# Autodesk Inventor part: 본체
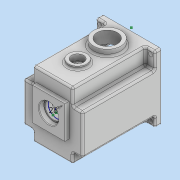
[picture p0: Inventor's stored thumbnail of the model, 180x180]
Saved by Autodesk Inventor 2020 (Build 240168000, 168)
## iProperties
Created: 2022-01
Part Number: 본체
Material: 일반
Document SubType Name: Modeling
Designer: user
Density: 1 g/cm^3
Appearance: 기본값
Author: user
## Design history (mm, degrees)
sketch "스케치1"
  geometry: 1 further point
sketch "스케치2"
  geometry: L1 (-49, 55)-(49, 55); L2 (49, 55)-(49, -55); L3 (49, -55)-(-49, -55); L4 (-49, -55)-(-49, 55); L5 (-49, 55)-(49, -55); L6 (49, 55)-(-49, -55); 1 further point
  constraints: 12 end point, 2 midpoint, 2 parallel, 1 horizontal, 1 perpendicular
  dimensions: "d0" = 98 distance of L2.end L3.end; "d1" = 110 distance of L1.end L2.end
extrude "돌출1" new body sketch "스케치2" distance "d2" = 10; taper "d3" = 0 deg
sketch "스케치3"
  geometry: L1 (49, -55)-(49, 55) reference; L2 (49, 55)-(-49, 55) reference; L3 (-49, 55)-(-49, -55) reference; L4 (-49, -55)-(49, -55) reference; L5 (49, -55)-(49, 55) reference; L6 (49, 55)-(33, 55); L7 (33, 55)-(33, 28); L8 (33, 28)-(49, 28); L9 (49, 28)-(49, 55); L10 (49, -55)-(33, -55); L11 (33, -55)-(33, -38); L12 (33, -38)-(49, -38); L13 (49, -38)-(49, -55); L14 (-49, -55)-(49, -55) reference; L15 (-49, -55)-(-33, -55); L16 (-33, -55)-(-33, -38); L17 (-33, -38)-(-49, -38); L18 (-49, -38)-(-49, -55); L19 (-49, 55)-(-49, -55) reference; L20 (-49, 55)-(-33, 55); L21 (-33, 55)-(-33, 28); L22 (-33, 28)-(-49, 28); L23 (-49, 28)-(-49, 55); 9 further points
  constraints: 32 end point, 8 parallel, 4 horizontal, 4 perpendicular, 1 point on line
  dimensions: "d4" = 27 distance of L6.end L7.end; "d5" = 16 distance of L7.end L8.end; "d6" = 17 distance of L10.end L11.end; "d7" = 16 distance of L11.end L12.end; "d8" = 27 distance of L20.end L21.end; "d9" = 16 distance of L21.end L22.end; "d10" = 16 distance of L16.end L17.end
extrude "돌출2" join sketch "스케치3" distance "d11" = 120; taper "d12" = 0 deg
sketch "스케치4"
  geometry: 1 further point
sketch "스케치5"
  geometry: L1 (49, -55)-(-49, -55) reference; L2 (-26, 48)-(26, 48); L3 (26, 48)-(26, 27.588); L4 (26, 27.588)-(-26, 27.588); L5 (-26, 27.588)-(-26, 48); C1 r 45 at (0, -5); 3 further points
  constraints: 8 end point, 2 parallel, 1 centre point, 1 horizontal, 1 perpendicular, 1 vertical alignment
  dimensions: "d13" = 90 diameter of C1; "d14" = 50 distance from line of L1 C1.centre; "d15" = 53 distance from line of L2 C1.centre; "d16" = 52 distance of L2.start L2.end; "d17" = 26 horizontal distance of C1.centre L2.start
extrude "돌출3" cut sketch "스케치5" distance "d18" = 9; taper "d19" = 0 deg
sketch "스케치6" dims "d27" = 8, "d28" = 8
  geometry: L1 (-26, 31.729)-(-26, 48) reference; L2 (26, 48)-(26, 31.729) reference; L3 (-26, 48)-(26, 48) reference; L4 (-23, 45)-(23, 45); L5 (23, 45)-(23, 21.058); L6 (23, 21.058)-(-23, 21.058); L7 (-23, 21.058)-(-23, 45); L8 (-35.778, -1.006)-(-41.81, -1.006); L9 (-35.778, -8.994)-(-41.81, -8.994); L10 (35.778, -1.006)-(42, -1.006); L11 (35.778, -8.994)-(41.81, -8.994); A1 r 45 centre (0, -5) between (-26, 31.729) and (26, 31.729) reference; A2 r 36 centre (0, -5) between (36, -5) and (-36, -5); A3 r 42 centre (0, -5) between (-41.81, -8.994) and (41.81, -8.994); A4 r 42 centre (0, -5) between (41.81, -1.006) and (-41.81, -1.006); 7 further points
  constraints: 16 end point, 10 point on circle, 4 horizontal, 3 centre point, 2 coincident, 2 horizontal alignment, 2 parallel, 1 perpendicular, 1 point on line, 6 other
  dimensions: "d21" = 46 distance of L4.start L4.end; "d22" = 23 distance from line of A1.centre L7; "d23" = 50 distance from line of A1.centre L4; "d26" = 72 diameter of A2
  node "투영된 루프2"
extrude "돌출4" cut sketch "스케치6" distance "d29" = 112; taper "d30" = 0 deg
fillet "모깎기1" dims "d31" = 3
sketch "스케치8"
  geometry: L1 (98, 0)-(0, 0) reference; C1 r 22.5 at (49, -40); C2 r 15 at (49, -89); 2 further points
  constraints: 2 centre point, 2 vertical alignment, 1 midpoint
  dimensions: "d32" = 45 diameter of C1; "d33" = 30 diameter of C2; "d34" = 40 distance of C1.centre point (49, 0); "d35" = 49 distance of C1.centre C2.centre
extrude "돌출5" join sketch "스케치8" distance "d36" = 10; taper "d37" = 0 deg
sketch "스케치9"
  geometry: C1 r 22.5 at (49, -40) reference; C2 r 15 at (49, -89); 1 further point
  constraints: 1 centre point, 1 vertical alignment
  dimensions: "d38" = 30 diameter of C2; "d39" = 49 distance of C1.centre C2.centre
extrude "돌출6" join sketch "스케치9" distance "d40" = 5; taper "d41" = 0 deg
sketch "스케치10"
  geometry: 1 further point
sketch "스케치11"
  geometry: C1 r 21 at (0, 6); C2 r 15 at (0, -25); C3 r 42 at (0, -5); A1 r 42 centre (0, -5) between (-23, 30.143) and (-41.319, 2.532) reference; 3 further points
  constraints: 3 centre point, 2 vertical alignment, 1 coincident
  dimensions: "d42" = 42 diameter of C1; "d43" = 30 diameter of C2; "d44" = 20 distance of C2.centre C3.centre; "d45" = 11 distance of C1.centre C3.centre
sketch "스케치12"
  geometry: C1 r 22.5 at (0, 0) reference; 2 further points
  constraints: 1 coincident
hole "구멍1" sketch "스케치12" at (0, 0) diameter "d46" = 33.376; stored, may be unused: countersink angle "d50" = 90 deg, drill point angle "d52" = 118 deg; dims "d47" = 70, "d48" = 4, "d49" = 2, "d51" = 77.3
extrude "돌출7" join sketch "스케치11" distance "d53" = 7; taper "d54" = 0 deg
sketch "스케치13"
  geometry: C1 r 11 at (0, -25); A1 r 15 centre (0, -25) between (-8.978, -12.984) and (8.978, -12.984) reference; 1 further point
  constraints: 1 centre point, 1 coincident
  dimensions: "d55" = 22 diameter of C1
extrude "돌출8" cut sketch "스케치13" distance "d56" = 7; taper "d57" = 0 deg
sketch "스케치14"
  geometry: C1 r 17.5 at (0, 6); A1 r 21 centre (0, 6) between (8.978, -12.984) and (-8.978, -12.984) reference; 1 further point
  constraints: 1 centre point, 1 coincident
  dimensions: "d58" = 35 diameter of C1
extrude "돌출9" cut sketch "스케치14" distance "d59" = 10; taper "d60" = 0 deg
sketch "스케치15"
  geometry: C1 r 11 at (0, 0) reference; C2 r 9.5 at (0, 0); 1 further point
  constraints: 1 centre point, 1 coincident
  dimensions: "d61" = 19 diameter of C2
extrude "돌출10" cut sketch "스케치15" distance "d62" = 3; taper "d63" = 0 deg
sketch "스케치16"
  geometry: C1 r 17.5 at (0, 0) reference; C2 r 14 at (0, 0); 1 further point
  constraints: 1 centre point, 1 coincident
  dimensions: "d64" = 28 diameter of C2
sketch "스케치17"
  geometry: 1 further point
sketch "스케치18"
  geometry: 1 further point
sketch "스케치19"
  geometry: L1 (-27, 33)-(27, 33); L2 (27, 33)-(27, -21); L3 (27, -21)-(-27, -21); L4 (-27, -21)-(-27, 33); L5 (-27, 33)-(27, -21); L6 (27, 33)-(-27, -21); 4 further points
  constraints: 12 end point, 3 midpoint, 2 parallel, 1 coincident, 1 horizontal, 1 perpendicular
  dimensions: "d65" = 54 distance of L2.end L3.end; "d66" = 54 distance of L1.end L2.end
extrude "돌출11" join sketch "스케치19" distance "d67" = 7; taper "d68" = 0 deg
sketch "스케치20"
  geometry: C1 r 16 at (0, 6); A1 r 21 centre (0, 6) between (8.978, -12.984) and (-8.978, -12.984) reference; 1 further point
  constraints: 1 centre point, 1 coincident
  dimensions: "d69" = 32 diameter of C1
extrude "돌출12" cut sketch "스케치20" distance "d70" = 8.3; taper "d71" = 0 deg
sketch "스케치21"
  geometry: C1 r 16 at (0, 0) reference; C2 r 14 at (0, 0); 1 further point
  constraints: 1 centre point, 1 coincident
  dimensions: "d72" = 28 diameter of C2
extrude "돌출13" cut sketch "스케치21" distance "d73" = 8.3; taper "d74" = 0 deg
sketch "스케치22"
  geometry: 1 further point
sketch "스케치23"
  geometry: C1 r 15 at (23, 80) reference; C2 r 15 at (23, 80); 1 further point
  constraints: 1 centre point, 1 coincident
  dimensions: "d75" = 30 diameter of C2
extrude "돌출14" cut sketch "스케치23" distance "d76" = 5; taper "d77" = 0 deg
sketch "스케치24"
  geometry: C1 r 15 at (0, 0) reference; C2 r 10 at (0, 0); 1 further point
  constraints: 1 centre point, 1 coincident
  dimensions: "d78" = 20 diameter of C2
extrude "돌출15" cut sketch "스케치24" stored distance "d79" = 5; taper "d80" = 0 deg
sketch "스케치25"
  geometry: L1 (33, -55)-(49, -55) reference; L2 (49, -55)-(49, -38) reference; L3 (-49, -38)-(-49, -55) reference; L4 (-49, -55)-(-33, -55) reference; L5 (-33, 55)-(-49, 55) reference; L6 (-49, 55)-(-49, 28) reference; L7 (49, 55)-(33, 55) reference; L8 (49, 28)-(49, 55) reference; C1 r 3.5 at (42, -48); C2 r 3.5 at (-42, -48); C3 r 3.5 at (-42, 48); C4 r 3.5 at (42, 48); 1 further point
  constraints: 4 centre point
  dimensions: "d81" = 7 diameter of C1; "d82" = 7 diameter of C2; "d83" = 7 diameter of C3; "d84" = 7 diameter of C4; "d85" = 7 distance from line of L1 C1.centre; "d86" = 7 distance from line of L2 C1.centre; "d87" = 7 distance from line of L3 C2.centre; "d88" = 7 distance from line of L4 C2.centre; "d89" = 7 distance from line of L5 C3.centre; "d90" = 7 distance from line of L6 C3.centre; "d91" = 7 distance from line of L7 C4.centre; "d92" = 7 distance from line of L8 C4.centre
extrude "돌출16" cut sketch "스케치25" distance "d93" = 10; taper "d94" = 0 deg
sketch "스케치26"
  geometry: A1 r 4 centre (-36, -5) between (-36.222, -8.994) and (-36.222, -1.006) reference; A2 r 4 centre (36, -5) between (36.222, -1.006) and (36.222, -8.994) reference; 3 further points
  constraints: 2 coincident
hole "구멍2" sketch "스케치26" at (-36, -5), (36, -5) diameter "d95" = 3.242; stored, may be unused: countersink angle "d99" = 90 deg, drill point angle "d101" = 118 deg; dims "d96" = 7, "d97" = 4, "d98" = 2, "d100" = 9
fillet "모깎기2" dims "d102" = 6
fillet "모깎기3" dims "d103" = 6
fillet "모깎기4" dims "d104" = 3
chamfer "모따기1" distance "d105" = 1; stored, may be unused: second distance "d106" = 2, angle "d107" = 45 deg
fillet "모깎기5" dims "d108" = 3
fillet "모깎기6" dims "d109" = 0.3
chamfer "모따기2" distance "d110" = 1; stored, may be unused: second distance "d111" = 2, angle "d112" = 45 deg
fillet "모깎기7" dims "d113" = 0.3
chamfer "모따기3" distance "d114" = 1; stored, may be unused: second distance "d115" = 2, angle "d116" = 45 deg
fillet "모깎기8" dims "d117" = 3
fillet "모깎기9" dims "d118" = 3
fillet "모깎기10" dims "d119" = 3
fillet "모깎기11" dims "d120" = 3
fillet "모깎기12" dims "d121" = 3
fillet "모깎기13" dims "d122" = 3
sketch "스케치27"
  geometry: 1 further point
fillet "모깎기14" dims "d123" = 3
sketch "스케치28"
  geometry: 1 further point
node "솔리드1"
node "투영된 루프1"
node "투영된 루프3"
feature "A9D066F2-1C7D-4E18-AEED-F7BC21143FA4" dims "d46" = 33.376, "d47" = 70, "d48" = 4, "d49" = 2, "d50" = 90 deg, "d51" = 77.3, "d52" = 118 deg
other parameters: "d20" = 84
